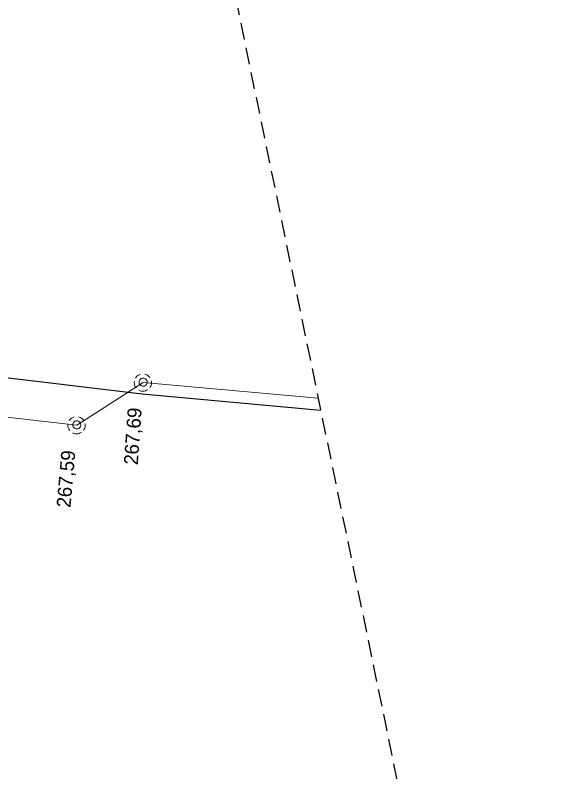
# Model space of a CAD drawing. Extents: x -732096 to -731933, y -1048703 to -1047964.
# Drawn here: x -731963.51 to -731932.91, y -1048660.19 to -1048616.96 of the extents above; entities that cross this region are included whole.
import ezdxf

# ---------------------------------------------------------------- set-up
doc = ezdxf.new("R2010")
doc.units = 0
doc.header["$LTSCALE"] = 0.32
doc.linetypes.add('MEDIUM_DASHED', pattern=[4.5, 3, -1.5])
doc.layers.add('1', color=7, linetype='Continuous')
for name, color, linetype, lineweight in [('18', 7, 'Continuous', 13), ('20', 7, 'Continuous', 13), ('63', 7, 'MEDIUM_DASHED', 25), ('8', 7, 'Continuous', 13)]:
    doc.layers.add(name, color=color, linetype=linetype, lineweight=lineweight)

msp = doc.modelspace()

# ---------------------------------------------------------------- linework, layer by layer
at = {"layer": '18'}
for points in [[(-731956.352, -1048637.477), (-731956.423, -1048637.505), (-731956.49, -1048637.544), (-731956.55, -1048637.592), (-731956.601, -1048637.649), (-731956.625, -1048637.683)], [(-731955.811, -1048637.66), (-731955.861, -1048637.602), (-731955.919, -1048637.552), (-731955.984, -1048637.511), (-731956.055, -1048637.482), (-731956.104, -1048637.468)], [(-731956.697, -1048637.869), (-731956.703, -1048637.946), (-731956.698, -1048638.023), (-731956.681, -1048638.098), (-731956.652, -1048638.169), (-731956.612, -1048638.235), (-731956.596, -1048638.257)], [(-731955.816, -1048638.246), (-731955.775, -1048638.181), (-731955.744, -1048638.111), (-731955.725, -1048638.036), (-731955.717, -1048637.96), (-731955.722, -1048637.883), (-731955.728, -1048637.848)], [(-731956.439, -1048638.386), (-731956.369, -1048638.417), (-731956.294, -1048638.436), (-731956.218, -1048638.443), (-731956.141, -1048638.438), (-731956.066, -1048638.421), (-731955.994, -1048638.393), (-731955.934, -1048638.358)], [(-731960.142, -1048639.916), (-731960.213, -1048639.944), (-731960.279, -1048639.983), (-731960.34, -1048640.031), (-731960.391, -1048640.088), (-731960.414, -1048640.122)], [(-731959.6, -1048640.099), (-731959.651, -1048640.041), (-731959.708, -1048639.991), (-731959.774, -1048639.95), (-731959.845, -1048639.921), (-731959.894, -1048639.907)], [(-731960.487, -1048640.308), (-731960.492, -1048640.385), (-731960.487, -1048640.462), (-731960.47, -1048640.537), (-731960.441, -1048640.608), (-731960.401, -1048640.674), (-731960.386, -1048640.696)], [(-731959.605, -1048640.685), (-731959.565, -1048640.62), (-731959.534, -1048640.55), (-731959.514, -1048640.475), (-731959.507, -1048640.399), (-731959.512, -1048640.322), (-731959.517, -1048640.287)], [(-731960.228, -1048640.825), (-731960.159, -1048640.856), (-731960.083, -1048640.875), (-731960.007, -1048640.882), (-731959.931, -1048640.877), (-731959.855, -1048640.86), (-731959.784, -1048640.832), (-731959.723, -1048640.797)]]:
    msp.add_lwpolyline(points, dxfattribs=at)
for points in [[(-731955.968, -1048637.929), (-731955.974, -1048637.877), (-731955.992, -1048637.827), (-731956.02, -1048637.783), (-731956.058, -1048637.746), (-731956.103, -1048637.719), (-731956.153, -1048637.703), (-731956.205, -1048637.698), (-731956.257, -1048637.705), (-731956.306, -1048637.724), (-731956.35, -1048637.754), (-731956.385, -1048637.793), (-731956.411, -1048637.838), (-731956.426, -1048637.889), (-731956.429, -1048637.941), (-731956.421, -1048637.993), (-731956.4, -1048638.041), (-731956.37, -1048638.084), (-731956.33, -1048638.119), (-731956.284, -1048638.143), (-731956.233, -1048638.157), (-731956.181, -1048638.159), (-731956.129, -1048638.149), (-731956.081, -1048638.127), (-731956.039, -1048638.095), (-731956.006, -1048638.055), (-731955.982, -1048638.008), (-731955.97, -1048637.957)], [(-731959.757, -1048640.368), (-731959.764, -1048640.316), (-731959.781, -1048640.266), (-731959.809, -1048640.222), (-731959.848, -1048640.185), (-731959.892, -1048640.158), (-731959.943, -1048640.142), (-731959.995, -1048640.137), (-731960.046, -1048640.144), (-731960.095, -1048640.163), (-731960.139, -1048640.193), (-731960.174, -1048640.232), (-731960.201, -1048640.277), (-731960.215, -1048640.328), (-731960.218, -1048640.38), (-731960.21, -1048640.432), (-731960.19, -1048640.48), (-731960.159, -1048640.523), (-731960.12, -1048640.558), (-731960.073, -1048640.582), (-731960.022, -1048640.596), (-731959.97, -1048640.598), (-731959.919, -1048640.588), (-731959.87, -1048640.566), (-731959.828, -1048640.534), (-731959.796, -1048640.494), (-731959.772, -1048640.447), (-731959.759, -1048640.396)]]:
    msp.add_lwpolyline(points, close=True, dxfattribs=at)
at = {"layer": '20'}
for p, q in [((-731956.199, -1048637.94), (-731959.989, -1048640.379)), ((-731956.199, -1048637.94), (-731959.989, -1048640.379)), ((-731946.199, -1048638.848), (-731956.199, -1048637.94)), ((-731946.199, -1048638.848), (-731956.199, -1048637.94)), ((-731959.989, -1048640.379), (-731976.76, -1048638.47)), ((-731959.989, -1048640.379), (-731976.76, -1048638.47))]:
    msp.add_line(p, q, dxfattribs=at)
at = {"layer": '63'}
msp.add_lwpolyline([(-732027.835, -1048396.578), (-731958.19, -1048580.745), (-731958.189, -1048580.746), (-731932.909, -1048703.246), (-731932.908, -1048703.248), (-731932.909, -1048703.25), (-731932.909, -1048703.251), (-731932.91, -1048703.253), (-731932.911, -1048703.255), (-731932.913, -1048703.256), (-731932.914, -1048703.257), (-731932.916, -1048703.257), (-731932.918, -1048703.258), (-731932.92, -1048703.258), (-732030.18, -1048688.546), (-732030.182, -1048688.545), (-732030.184, -1048688.545), (-732030.185, -1048688.543), (-732030.186, -1048688.542), (-732030.187, -1048688.54), (-732030.188, -1048688.538), (-732095.318, -1048413.733)], dxfattribs=at)
at = {"layer": '8', "lineweight": 25}
msp.add_lwpolyline([(-731978.579, -1048636.27), (-731974.02, -1048636.56), (-731968.19, -1048637.159), (-731956.25, -1048638.6), (-731946.058, -1048639.529)], dxfattribs=at)

# ---------------------------------------------------------------- texts
at = {"layer": '1'}
for s, rotation, p in [('267,69', 86, (-731956.501, -1048642.677)), ('267,59', 85, (-731960.347, -1048645.121))]:
    msp.add_text(s, height=0.8, rotation=rotation, dxfattribs=at).set_placement(p)

doc.saveas('drawing.dxf')
